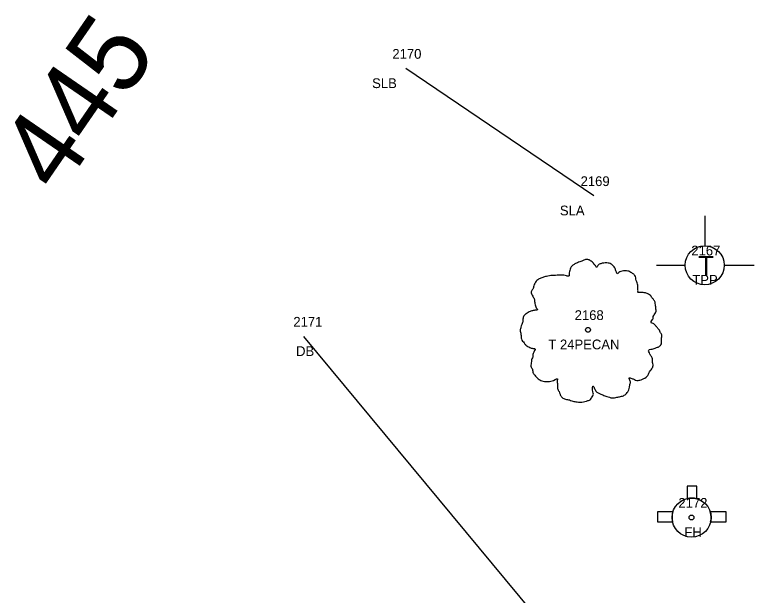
# Model space of a CAD drawing. Extents: x 2266664 to 2272542, y 716533 to 724777.
# Drawn here: x 2271790.3 to 2271866, y 724090.3 to 724149.7 of the extents above; entities that cross this region are included whole.
import ezdxf

# ---------------------------------------------------------------- set-up
doc = ezdxf.new("R2010")
doc.units = 0
for name, color, linetype in [('RD_EX_Driveway', 7, 'Continuous'), ('RD_EX_Driveway_txCode', 7, 'Continuous'), ('RD_EX_UT', 7, 'Continuous'), ('RD_EX_UT_txCode', 7, 'Continuous'), ('RD_EX_VEG', 7, 'Continuous'), ('RD_EX_VEG_txCode', 7, 'Continuous'), ('RD_HC_TX_Sta50', 7, 'Continuous'), ('RD_SMD_Locator', 7, 'Continuous')]:
    doc.layers.add(name, color=color, linetype=linetype)

msp = doc.modelspace()

# ---------------------------------------------------------------- linework, layer by layer
at = {"layer": 'RD_EX_Driveway'}
msp.add_line((2271845.335, 724086.097), (2271819.867, 724116.758), dxfattribs=at)
at = {"layer": 'RD_EX_UT'}
for p, q in [((2271860.902, 724129.118), (2271860.902, 724126.048)), ((2271855.971, 724124.064), (2271858.902, 724124.064)), ((2271862.902, 724124.064), (2271865.971, 724124.064)), ((2271859.102, 724101.445), (2271859.102, 724100.171)), ((2271860.102, 724101.445), (2271859.102, 724101.445)), ((2271860.102, 724100.148), (2271860.102, 724101.445)), ((2271857.643, 724098.797), (2271856.085, 724098.797)), ((2271856.085, 724098.797), (2271856.085, 724097.797)), ((2271863.085, 724098.797), (2271861.475, 724098.797)), ((2271863.085, 724097.797), (2271863.085, 724098.797)), ((2271856.085, 724097.797), (2271857.605, 724097.797)), ((2271861.513, 724097.797), (2271863.085, 724097.797))]:
    msp.add_line(p, q, dxfattribs=at)
for centre, radius in [((2271860.902, 724124.048), 2), ((2271859.559, 724098.224), 2), ((2271859.559, 724098.224), 0.25)]:
    msp.add_circle(centre, radius, dxfattribs=at)
for start, end in [(74.24553, 103.21276), (163.3387, 192.31502), (347.68498, 16.6613)]:
    msp.add_arc((2271859.559, 724098.224), 2, start, end, dxfattribs=at)
at = {"layer": 'RD_EX_VEG'}
msp.add_line((2271849.573, 724131.15), (2271830.325, 724144.178), dxfattribs=at)
for centre, radius in [((2271848.965, 724117.439), 0.25), ((2271848.952, 724117.42), 0.0001)]:
    msp.add_circle(centre, radius, dxfattribs=at)
for points in [[(2271849.097, 724124.606), (2271848.797, 724124.631), (2271848.472, 724124.531), (2271848.222, 724124.431), (2271847.997, 724124.356), (2271847.772, 724124.256), (2271847.472, 724124.082), (2271847.247, 724123.882), (2271847.122, 724123.632), (2271847.072, 724123.407), (2271847.023, 724123.132), (2271847.023, 724122.957), (2271846.898, 724122.932), (2271846.748, 724122.957), (2271846.498, 724123.032), (2271846.248, 724123.032), (2271845.998, 724123.032), (2271845.648, 724123.007), (2271845.298, 724123.007), (2271845.023, 724122.957), (2271844.699, 724122.907), (2271844.324, 724122.782), (2271843.974, 724122.657), (2271843.674, 724122.407), (2271843.424, 724121.933), (2271843.299, 724121.583), (2271843.149, 724121.333), (2271843.299, 724120.883), (2271843.474, 724120.533), (2271843.499, 724120.333), (2271843.574, 724119.908), (2271843.674, 724119.684), (2271843.799, 724119.484), (2271843.724, 724119.459), (2271843.349, 724119.409), (2271843.049, 724119.309), (2271842.624, 724119.084), (2271842.4, 724118.859), (2271842.3, 724118.534), (2271842.275, 724118.184), (2271842.175, 724117.984), (2271842.1, 724117.709), (2271842.075, 724117.634), (2271842.025, 724117.31), (2271842.125, 724116.86), (2271842.15, 724116.51), (2271842.275, 724116.285), (2271842.425, 724116.11), (2271842.599, 724115.86), (2271842.999, 724115.635), (2271843.324, 724115.535), (2271843.524, 724115.51), (2271843.349, 724115.011), (2271843.299, 724114.661), (2271843.174, 724114.261), (2271843.174, 724114.186), (2271843.124, 724113.711), (2271843.274, 724113.386), (2271843.349, 724113.011), (2271843.524, 724112.787), (2271843.799, 724112.487), (2271844.124, 724112.262), (2271844.624, 724112.137), (2271845.023, 724112.162), (2271845.598, 724112.337), (2271845.848, 724112.412), (2271845.823, 724112.237), (2271845.848, 724111.862), (2271845.848, 724111.437), (2271845.998, 724111.112), (2271846.098, 724110.837), (2271846.248, 724110.587), (2271846.573, 724110.363), (2271846.973, 724110.288), (2271847.397, 724110.138), (2271847.847, 724110.063), (2271848.347, 724110.038), (2271848.947, 724110.188), (2271849.222, 724110.313), (2271849.322, 724110.488), (2271849.521, 724110.862), (2271849.471, 724111.087), (2271849.496, 724111.687), (2271849.596, 724111.512), (2271849.771, 724111.162), (2271850.271, 724110.862), (2271850.671, 724110.687), (2271851.146, 724110.537), (2271851.446, 724110.463), (2271851.92, 724110.537), (2271852.295, 724110.612), (2271852.67, 724110.737), (2271852.97, 724111.012), (2271853.145, 724111.287), (2271853.195, 724111.562), (2271853.27, 724111.937), (2271853.32, 724112.112)], [(2271853.32, 724112.112), (2271853.245, 724112.287), (2271853.195, 724112.537), (2271853.27, 724112.512), (2271853.445, 724112.462), (2271853.72, 724112.337), (2271853.945, 724112.262), (2271854.269, 724112.287), (2271854.544, 724112.387), (2271854.994, 724112.662), (2271855.269, 724113.136), (2271855.544, 724113.536), (2271855.619, 724113.861), (2271855.569, 724114.086), (2271855.544, 724114.586), (2271855.344, 724114.836), (2271855.294, 724114.961), (2271855.194, 724115.36), (2271855.269, 724115.41), (2271855.544, 724115.46), (2271855.919, 724115.585), (2271856.194, 724115.71), (2271856.418, 724115.885), (2271856.493, 724116.11), (2271856.468, 724116.51), (2271856.518, 724116.91), (2271856.443, 724117.06), (2271856.343, 724117.21), (2271856.268, 724117.41), (2271856.119, 724117.559), (2271856.019, 724117.709), (2271855.919, 724117.809), (2271855.794, 724117.959), (2271855.619, 724118.084), (2271855.469, 724118.134), (2271855.419, 724118.284), (2271855.569, 724118.484), (2271855.619, 724118.584), (2271855.644, 724118.809), (2271855.869, 724119.159), (2271855.919, 724119.559), (2271855.869, 724119.983), (2271855.819, 724120.258), (2271855.669, 724120.533), (2271855.469, 724120.783), (2271855.344, 724120.958), (2271855.169, 724121.083), (2271854.844, 724121.208), (2271854.594, 724121.258), (2271854.244, 724121.258), (2271854.044, 724121.308), (2271854.069, 724121.358), (2271854.069, 724121.508), (2271854.069, 724121.783), (2271853.994, 724122.232), (2271853.845, 724122.732), (2271853.845, 724122.757), (2271853.745, 724123.007), (2271853.52, 724123.207), (2271853.345, 724123.307), (2271853.145, 724123.432), (2271852.895, 724123.457), (2271852.595, 724123.457), (2271852.32, 724123.407), (2271852.12, 724123.307), (2271851.945, 724123.182), (2271851.87, 724123.332), (2271851.77, 724123.632), (2271851.72, 724123.782), (2271851.571, 724123.957), (2271851.346, 724124.157), (2271850.896, 724124.281), (2271850.271, 724124.207), (2271849.971, 724124.007), (2271849.821, 724123.832), (2271849.771, 724123.957), (2271849.571, 724124.157), (2271849.471, 724124.331), (2271849.297, 724124.456), (2271849.147, 724124.556), (2271849.047, 724124.606)]]:
    msp.add_spline(points, degree=3, dxfattribs=at)
at = {"layer": 'RD_SMD_Locator'}
for centre in [(2271830.325, 724144.178), (2271849.573, 724131.15), (2271819.867, 724116.758)]:
    msp.add_circle(centre, 0.001, dxfattribs=at)

# ---------------------------------------------------------------- texts
at = {"layer": 'RD_EX_Driveway_txCode'}
for s, p in [('2171', (2271818.804, 724117.758)), ('DB', (2271819.087, 724114.758))]:
    msp.add_text(s, height=1, dxfattribs=at).set_placement(p)
at = {"layer": 'RD_EX_UT'}
msp.add_text('T', height=2, dxfattribs=at).set_placement((2271860.232, 724123.001))
at = {"layer": 'RD_EX_UT_txCode'}
for s, p in [('2167', (2271859.532, 724125.048)), ('TPP', (2271859.634, 724122.048)), ('2172', (2271858.212, 724099.224)), ('FH', (2271858.827, 724096.224))]:
    msp.add_text(s, height=1, dxfattribs=at).set_placement(p)
at = {"layer": 'RD_EX_VEG_txCode'}
for s, p in [('2170', (2271828.939, 724145.178)), ('SLB', (2271826.869, 724142.178)), ('2169', (2271848.203, 724132.15)), ('SLA', (2271846.085, 724129.15)), ('2168', (2271847.595, 724118.439)), ('T 24PECAN', (2271844.902, 724115.439))]:
    msp.add_text(s, height=1, dxfattribs=at).set_placement(p)
at = {"layer": 'RD_HC_TX_Sta50'}
msp.add_text('445', height=8, rotation=55.46633, dxfattribs=at).set_placement((2271794.842, 724131.163))

doc.saveas('drawing.dxf')
